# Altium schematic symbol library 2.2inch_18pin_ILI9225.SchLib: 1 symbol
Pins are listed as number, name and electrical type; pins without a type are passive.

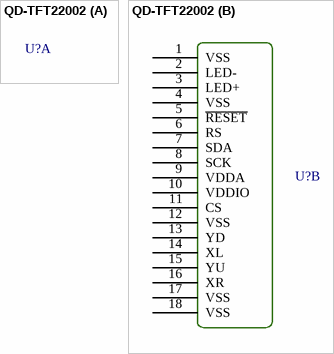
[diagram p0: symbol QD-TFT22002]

## QD-TFT22002
designator U?  (value not drawn)
part B pins: 1 VSS, 2 LED-, 3 LED+, 4 VSS, 5 ~{RESET}, 6 RS, 7 SDA, 8 SCK, 9 VDDA, 10 VDDIO, 11 CS, 12 VSS, 13 YD, 14 XL, 15 YU, 16 XR, 17 VSS, 18 VSS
